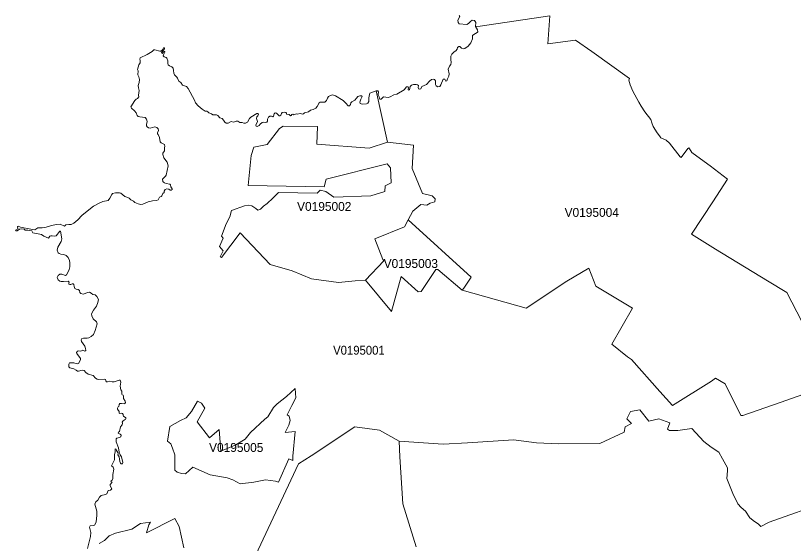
# Model space of a CAD drawing. Extents: x 369010 to 735936, y 6377141 to 6616555.
# Drawn here: x 470305 to 479041, y 6502081 to 6508010 of the extents above; entities that cross this region are included whole.
import ezdxf
from ezdxf.enums import TextEntityAlignment as Align

# ---------------------------------------------------------------- set-up
doc = ezdxf.new("R2010")
doc.units = 0
doc.header["$LTSCALE"] = 40
doc.layers.add('3', color=7, linetype='Continuous', lineweight=13)
doc.layers.add('4', color=7, linetype='Continuous')

msp = doc.modelspace()

# ---------------------------------------------------------------- linework, layer by layer
at = {"layer": '3'}
for points in [[(475288.27, 6508011.78), (475293.89, 6507998.38), (475271.55, 6507958.16), (475274.86, 6507932.51), (475287.77, 6507916.95), (475371.52, 6507910.83), (475391.54, 6507920.26), (475412.73, 6507943.1), (475434.57, 6507957.66), (475457.91, 6507953.69), (475473.63, 6507933.67), (475469.49, 6507887.82), (475469.66, 6507887.82), (475521.79, 6507889.64), (476305.45, 6508008.47), (476281.79, 6507693.85), (476592.44, 6507732.91), (476778.13, 6507606.13), (477199.34, 6507304.42), (477191.73, 6507284.23), (477208.44, 6507231.27), (477235.92, 6507159.44), (477303.94, 6507035.81), (477330.59, 6506992.78), (477372.46, 6506926.91), (477439.32, 6506841.67), (477450.25, 6506804.43), (477464.31, 6506764.71), (477509.5, 6506694.54), (477535.15, 6506657.3), (477551.04, 6506638.43), (477612.44, 6506611.45), (477647.69, 6506578.52), (477767.19, 6506423.28), (477781.75, 6506415.33), (477855.57, 6506515.63), (477864.67, 6506525.39), (477887.18, 6506490.14), (477899.92, 6506472.1), (478080.49, 6506340.86), (478106.47, 6506321.82), (478300.61, 6506172.7), (478134.11, 6505918.32), (477897.44, 6505555.54), (478166.55, 6505386.23), (478748.13, 6505031.55), (478968.25, 6504900.47), (479245.14, 6504363.08)], [(479245.14, 6504363.08), (478968.25, 6504900.47), (478748.13, 6505031.55), (478166.55, 6505386.23), (477897.44, 6505555.54), (478134.11, 6505918.32), (478300.61, 6506172.7), (478106.47, 6506321.82), (478080.49, 6506340.86), (477899.92, 6506472.1), (477887.18, 6506490.14), (477864.67, 6506525.39), (477855.57, 6506515.63), (477781.75, 6506415.33), (477767.19, 6506423.28), (477647.69, 6506578.52), (477612.44, 6506611.45), (477551.04, 6506638.43), (477535.15, 6506657.3), (477509.5, 6506694.54), (477464.31, 6506764.71), (477450.25, 6506804.43), (477439.32, 6506841.67), (477372.46, 6506926.91), (477330.59, 6506992.78), (477303.94, 6507035.81), (477235.92, 6507159.44), (477208.44, 6507231.27), (477191.73, 6507284.23), (477199.34, 6507304.42), (476778.13, 6507606.13), (476592.44, 6507732.91), (476281.79, 6507693.85), (476305.45, 6508008.47), (475521.79, 6507889.64), (475469.66, 6507887.82), (475469.49, 6507887.66)], [(475469.49, 6507887.66), (475493.16, 6507848.27), (475496.97, 6507828.07), (475490.84, 6507819.3), (475450.13, 6507797.95), (475438.38, 6507785.71), (475435.07, 6507748.3), (475418.85, 6507705.44), (475387.07, 6507666.38), (475351.99, 6507641.72), (475331.79, 6507637.25), (475313.92, 6507645.19), (475292.74, 6507660.75), (475282.14, 6507661.91), (475268.74, 6507650.65), (475263.28, 6507633.44), (475250.37, 6507615.07), (475231.33, 6507602.66), (475204.03, 6507577.67), (475194.59, 6507552.51), (475193.43, 6507516.76), (475197.57, 6507483), (475193.1, 6507461.81), (475176.88, 6507439.97), (475164.64, 6507408.85), (475173.57, 6507355.23), (475169.6, 6507330.74), (475157.35, 6507298.3), (475146.76, 6507276.62), (475138.98, 6507274.3), (475125.58, 6507297.14), (475108.2, 6507295.48), (475080.73, 6507232.76), (475069.14, 6507213.23), (475048.45, 6507210.41), (475028.26, 6507219.35), (475020.48, 6507234.91), (475020.48, 6507276.78), (475010.55, 6507291.35), (474994.33, 6507296.97), (474977.62, 6507292.5), (474955.27, 6507273.47), (474921.68, 6507236.56), (474867.56, 6507212.07), (474854.81, 6507188.73), (474843.56, 6507181.95), (474831.31, 6507188.73), (474826.84, 6507203.79), (474829.66, 6507223.32), (474820.22, 6507232.26), (474805.66, 6507237.23), (474772.23, 6507236.56), (474751.54, 6507227.13), (474737.64, 6507214.39), (474731.51, 6507195.35), (474729.86, 6507175.33), (474719.76, 6507171.35), (474715.29, 6507175.82), (474719.26, 6507203.13), (474713.14, 6507210.41), (474695.27, 6507209.92), (474669.61, 6507177.48), (474588.02, 6507126.17), (474554.09, 6507120.71), (474512.72, 6507098.37), (474489.21, 6507089.43), (474438.57, 6507098.37), (474410.1, 6507070.4), (474397.19, 6507070.4), (474392.73, 6507081.65), (474389.42, 6507098.86), (474378.16, 6507120.71), (474379.32, 6507151.99), (474373.2, 6507164.24), (474355.98, 6507163.58), (474483.92, 6506587.46), (474774.71, 6506552.7), (474759.32, 6506291.7), (474874.51, 6506012.5), (474982.25, 6505984.36), (475017.67, 6505950.93), (475013.2, 6505918.16), (474961.73, 6505902.27), (474924.49, 6505881.09), (474856.96, 6505888.04), (474768.09, 6505811.24), (474715.29, 6505715.25), (475421.99, 6505070.12), (475339.74, 6504946.82), (475321.04, 6504926.29), (476037.83, 6504724.21), (476497.44, 6505027.58), (476744.54, 6505173.39), (476822.82, 6504971.31), (477233.1, 6504724.87), (477000.08, 6504320.05), (477178.82, 6504175.24), (477221.19, 6504145.61), (477540.78, 6503787.63), (477682.78, 6503631.72)], [(471975.04, 6507649.16), (471967.76, 6507646.35), (471954.19, 6507624.17), (471936.31, 6507608.45), (471925.72, 6507608.45), (471870.44, 6507625.17), (471856.54, 6507623.51), (471837.51, 6507607.95), (471782.4, 6507573.86), (471704.77, 6507535.96), (471701.96, 6507520.24), (471705.27, 6507503.52), (471704.77, 6507480.19), (471690.87, 6507455.53), (471676.31, 6507404.72), (471680.28, 6507387.5), (471678.63, 6507342.65), (471688.72, 6507320.47), (471695.84, 6507292.5), (471693.69, 6507257.91), (471681.44, 6507226.14), (471684.75, 6507198.17), (471693.19, 6507169.7), (471686.4, 6507116.24), (471690.38, 6507097.71), (471675.31, 6507077.18), (471660.75, 6507069.9), (471643.54, 6507055.34), (471600.51, 6506985.66), (471606.13, 6506968.28), (471640.06, 6506938.16), (471657.94, 6506915.82), (471671.84, 6506888.01), (471683.59, 6506875.6), (471700.31, 6506871.3), (471760.05, 6506866.83), (471776.77, 6506847.79), (471781.24, 6506819.33), (471773.96, 6506788.05), (471774.62, 6506769.68), (471781.57, 6506760.57), (471798.28, 6506749.98), (471817.81, 6506745.51), (471867.47, 6506758.42), (471891.46, 6506752.3), (471906.52, 6506737.24), (471909.83, 6506717.71), (471899.9, 6506691.39), (471898.75, 6506680.3), (471907.19, 6506674.18), (471919.93, 6506641.25), (471929.36, 6506590.93), (471938.96, 6506579.84), (471977.36, 6506560.81), (471981.83, 6506540.78), (471976.86, 6506526.88), (471977.36, 6506492.29), (471960.15, 6506464.82), (471957.33, 6506448.76), (471971.24, 6506410.7), (472008.64, 6506362.21), (472018.74, 6506321.49), (471997.55, 6506218.22), (471989.11, 6506205.31), (471972.39, 6506191.41), (471956.18, 6506170.72), (471958.49, 6506147.88), (471965.77, 6506137.78), (471979.18, 6506130.5), (471998.05, 6506123.38), (472036.61, 6506117.26), (472046.54, 6506107.66), (472048.36, 6506088.13), (472062.76, 6506065.29), (472062.26, 6506055.2), (472054.48, 6506049.07), (472043.23, 6506049.73), (472027.01, 6506058.67), (472004.83, 6506062.97), (471986.3, 6506055.86), (471973.55, 6506038.48), (471972.39, 6506021.76), (471958.99, 6506013.32), (471949.56, 6505986.68), (471940.12, 6505977.74), (471922.74, 6505969.3), (471907.19, 6505941.49), (471889.31, 6505932.56), (471841.32, 6505928.59), (471794.97, 6505918.49), (471735.89, 6505890.69), (471712.88, 6505886.22), (471682.27, 6505894), (471645.36, 6505911.21), (471630.3, 6505925.77), (471598.52, 6505941.99), (471580.15, 6505960.36), (471565.09, 6505968.14), (471532.15, 6505977.57), (471486.97, 6506016.14)], [(472887.8, 6506799.63), (472867.61, 6506801.78), (472850.39, 6506810.72), (472824.74, 6506810.72), (472802.4, 6506824.13), (472782.21, 6506825.29), (472752.08, 6506814.03), (472727.59, 6506819.16), (472692.5, 6506802.94), (472671.15, 6506802.45), (472656.09, 6506813.04), (472642.19, 6506835.22), (472624.31, 6506852.59), (472600.98, 6506861.03), (472576.32, 6506886.03), (472562.42, 6506893.31), (472519.88, 6506894.63), (472505.98, 6506904.73), (472474.7, 6506915.82), (472465.76, 6506927.07), (472454.67, 6506934.35), (472435.14, 6506936.5), (472400.55, 6506958.35), (472357.52, 6506994.6), (472327.4, 6507028.69), (472315.82, 6507059.81), (472244.32, 6507190.39), (472225.95, 6507211.57), (472180.76, 6507227.3), (472160.9, 6507256.92), (472139.72, 6507271.98), (472125.15, 6507305.41), (472115.72, 6507319.48), (472088.25, 6507345.63), (472081.13, 6507364), (472079.48, 6507393.13), (472073.85, 6507417.62), (472060.44, 6507432.69), (472032.47, 6507446.09), (472019.73, 6507457.84), (472015.76, 6507470.59), (472014.1, 6507501.87), (472005.16, 6507533.15), (471995.07, 6507540.43), (471975.54, 6507547.05), (471963.95, 6507556.65), (471965.61, 6507568.9), (471982.82, 6507598.36), (471982.82, 6507606.3), (471975.04, 6507606.8), (471966.11, 6507601.17), (471953.86, 6507584.45), (471946.58, 6507587.27), (471944.92, 6507595.71), (471977.86, 6507638.08), (471979.01, 6507645.36), (471975.04, 6507649.16)], [(472918.08, 6506101.21), (472950.52, 6506437.34), (472981.31, 6506530.52), (473129.27, 6506562.13), (473270.77, 6506740.22), (473309.34, 6506767.19), (473695.29, 6506764.88), (473688.67, 6506566.77), (474275.88, 6506519.27), (474483.92, 6506587.46), (474355.98, 6507163.58), (474284.49, 6507137.43), (474278.36, 6507122.37), (474271.74, 6507086.62), (474270.58, 6507044.74), (474262.8, 6507027.53), (474247.74, 6507017.44), (474197.43, 6507015.78), (474174.59, 6507021.9), (474169.63, 6507039.12), (474181.21, 6507069.9), (474196.93, 6507099.53), (474190.81, 6507110.12), (474169.63, 6507110.12), (474148.94, 6507100.02), (474135.04, 6507080.49), (474114.35, 6507061.46), (474082.57, 6507041.43), (474071.81, 6507029.68), (474066.85, 6507011.31), (474056.75, 6506996.75), (474041.19, 6506994.43), (474013.72, 6507026.87), (473983.1, 6507055.83), (473898.86, 6507108.3), (473864.27, 6507119.55), (473843.58, 6507113.93), (473817.93, 6507101.02), (473807.83, 6507080.99), (473795.59, 6507056.99), (473779.37, 6507038.62), (473726.41, 6507037.96), (473714.16, 6507029.19), (473691.32, 6506987.31), (473677.42, 6506969.44), (473645.47, 6506953.72), (473618.17, 6506947.1), (473593.67, 6506927.57), (473548.99, 6506917.8), (473538.89, 6506904.89), (473529.46, 6506901.58), (473516.05, 6506907.71), (473500.49, 6506908.87), (473467.56, 6506901.58), (473454.65, 6506907.21), (473428.5, 6506896.12), (473417.91, 6506901.58), (473408.31, 6506897.11), (473401.69, 6506886.03), (473392.75, 6506882.72), (473377.69, 6506900.42), (473348.06, 6506901.09), (473347.57, 6506912.84), (473339.79, 6506921.11), (473320.76, 6506925.58), (473300.07, 6506921.11), (473291.79, 6506910.02), (473284.01, 6506889.83), (473274.41, 6506883.21), (473264.98, 6506883.21), (473237.01, 6506913.33), (473221.95, 6506915.65), (473209.7, 6506907.71), (473203.08, 6506879.9), (473195.8, 6506873.78), (473177.93, 6506879.24), (473159.55, 6506879.9), (473145.65, 6506869.81), (473133.9, 6506847.46), (473134.89, 6506824.13), (473125.96, 6506811.71), (473115.37, 6506809.07), (473090.37, 6506813.54), (473076.31, 6506809.07), (473052.97, 6506791.69), (473039.56, 6506776.63), (473016.56, 6506765.04), (473005.97, 6506768.35), (473003.15, 6506778.28), (473021.69, 6506819.66), (473011.1, 6506855.41), (473016.06, 6506870.97), (473026.66, 6506884.37), (473032.78, 6506900.09), (473026.66, 6506908.87), (473015.57, 6506911.68), (472946.39, 6506869.81), (472933.48, 6506855.41), (472908.98, 6506813.04), (472887.8, 6506799.63)], [(479283.53, 6503802.02), (478892.78, 6503665.32), (478472.07, 6503516.7), (478451.55, 6503519.34), (478273.3, 6503873.85), (478166.22, 6503937.9), (478121.36, 6503902.49), (477682.78, 6503631.72), (477540.78, 6503787.63), (477221.19, 6504145.61), (477178.82, 6504175.24), (477000.08, 6504320.05), (477233.1, 6504724.87), (476822.82, 6504971.31), (476744.54, 6505173.39), (476497.44, 6505027.58), (476037.83, 6504724.21), (475321.04, 6504926.29), (475046.47, 6505157.83), (475026.44, 6505156.51), (474861.93, 6504911.56), (474827.84, 6504907.76), (474633.7, 6505077.89), (474525.29, 6504686.31), (474234.5, 6505037.35), (474117.66, 6505030.56), (473933.29, 6505011.2), (473630.41, 6505054.56), (473411.78, 6505142.44), (473164.85, 6505213.28), (472828.71, 6505567.95), (472617.2, 6505291.73), (472604.45, 6505300), (472636.07, 6505368.69), (472594.86, 6505415.03), (472635.73, 6505510.69), (472618.85, 6505533.2), (472669.17, 6505671.72), (472710.05, 6505747.52), (472729.91, 6505822.33), (472876.87, 6505873.14), (472918.75, 6505880.42), (472958.63, 6505872.15), (473002.33, 6505841.2), (473025, 6505823.82), (473054.63, 6505834.08), (473089.38, 6505867.68), (473131.42, 6505898.79), (473193.65, 6505958.87), (473258.86, 6506024.25), (473691.48, 6506013.49), (473724.92, 6506050.07), (473790.13, 6506034.51), (473878.17, 6505971.29), (474293.09, 6505985.19), (474450.65, 6506035.17), (474455.95, 6506098.06), (474524.14, 6506129.67), (474516.85, 6506300.97), (474478.95, 6506342.84), (473793.1, 6506171.21), (473771.42, 6506086.81), (472918.08, 6506101.21)], [(471486.97, 6506016.14), (471471.25, 6506019.45), (471427.22, 6506017.3), (471394.29, 6506010.01), (471386.01, 6505999.92), (471365.33, 6505959.2), (471343.48, 6505933.55), (471284.89, 6505920.14), (471242.52, 6505902.93), (471180.13, 6505867.68), (471126.5, 6505829.28), (471050.04, 6505765.73), (471003.2, 6505716.08), (470958.02, 6505676.52), (470927.9, 6505663.12), (470901.58, 6505663.12), (470871.46, 6505658.65), (470853.09, 6505645.9), (470804.93, 6505667.92), (470763.72, 6505663.94), (470707.12, 6505651.37), (470648.86, 6505633.99), (470605.17, 6505627.04), (470553.53, 6505626.71), (470520.59, 6505604.03), (470476.9, 6505609), (470359.23, 6505633.49), (470335.89, 6505643.75), (470326.62, 6505638.95), (470329.27, 6505613.13), (470305.11, 6505598.74), (470306.6, 6505591.62), (470323.81, 6505593.77), (470350.79, 6505610.65), (470369.82, 6505613.96), (470399.94, 6505610.16), (470412.69, 6505599.89), (470427.41, 6505598.07), (470443.97, 6505600.72), (470487.49, 6505590.46), (470498.91, 6505571.26), (470595.4, 6505550.57), (470622.54, 6505531.38), (470675.67, 6505510.19), (470691.23, 6505531.54), (470700.83, 6505537), (470717.21, 6505537), (470740.38, 6505531.87), (470761.57, 6505535.18), (470801.95, 6505589.47), (470808.74, 6505587.15), (470825.78, 6505503.07), (470818.67, 6505472.13), (470779.94, 6505407.74), (470773.98, 6505373.82), (470783.74, 6505346.01), (470795.66, 6505335.75), (470814.2, 6505329.79), (470847.46, 6505325.32), (470874.28, 6505314.4), (470896.12, 6505292.55), (470910.19, 6505258.29), (470914, 6505233.8), (470914, 6505187.29), (470907.54, 6505156.67), (470897.78, 6505131.02), (470877.59, 6505096.76), (470866.17, 6505088.98), (470824.13, 6505103.71), (470801.78, 6505104.38), (470783.74, 6505092.29), (470772.33, 6505067.8), (470784.9, 6505042.15), (470801.29, 6505028.57), (470818.67, 6505024.11), (470843.82, 6505021.95), (470897.28, 6505025.26), (470908.7, 6505017.15), (470904.23, 6505005.07), (470904.89, 6504994.65), (470914.66, 6504989.85), (470925.58, 6504989.85), (470939.15, 6504998.45), (470953.88, 6504996.96), (470959.34, 6504988.19), (470962.16, 6504966.84), (470972.42, 6504945.66), (470987.15, 6504935.89), (471009.49, 6504931.92), (471021.57, 6504920.5), (471027.04, 6504898.65), (471038.95, 6504886.74), (471064.11, 6504881.77), (471115.41, 6504900.97), (471137.1, 6504903.12), (471155.14, 6504893.36), (471172.02, 6504877.97), (471199.33, 6504871.51), (471218.36, 6504853.47), (471236.89, 6504821.36)], [(471236.89, 6504821.36), (471229.94, 6504788.59), (471214.06, 6504747.71), (471180.79, 6504700.21), (471159.6, 6504659.34), (471160.1, 6504635.83), (471176.49, 6504602.57), (471212.4, 6504568.8), (471222.83, 6504545.8), (471199.82, 6504474.3), (471179.13, 6504427.96), (471154.64, 6504404.62), (471128.49, 6504390.89), (471110.95, 6504387.58), (471069.57, 6504388.24), (471050.54, 6504381.12), (471042.26, 6504367.55), (471046.73, 6504350.01), (471083.8, 6504298.21), (471092.41, 6504272.06), (471094.73, 6504249.22), (471084.8, 6504240.94), (471059.14, 6504251.86), (471044.41, 6504243.75), (471029.68, 6504239.78), (471014.46, 6504244.75), (471001.38, 6504240.94), (470989.96, 6504226.71), (470993.27, 6504213.14), (471032.99, 6504158.02), (471035.15, 6504142.3), (471011.15, 6504103.57), (470998.07, 6504099.77), (470959.34, 6504110.03), (470926.08, 6504111.19), (470909.69, 6504107.88), (470903.24, 6504095.3), (470903.74, 6504065.34), (470914.16, 6504054.42), (470958.85, 6504041.84), (470984, 6504028.77), (470999.23, 6504016.85), (471012.31, 6504016.85), (471052.85, 6504027.61), (471074.7, 6504023.8), (471095.39, 6504000.3), (471119.39, 6503984.08), (471176.15, 6503967.03), (471203.96, 6503937.08), (471222, 6503926.15), (471237.72, 6503924), (471303.76, 6503927.31), (471315.18, 6503920.69), (471320.14, 6503906.62), (471328.25, 6503897.85), (471338.02, 6503896.69), (471365.33, 6503904.97), (471388.33, 6503897.85), (471411.67, 6503897.85), (471467.94, 6503913.57), (471478.86, 6503914.24), (471485.32, 6503905.46), (471486.47, 6503890.73), (471479.85, 6503847.7), (471488.63, 6503804.51), (471497.4, 6503791.43), (471496.74, 6503757.17), (471502.86, 6503748.4), (471513.62, 6503744.59), (471518.09, 6503739.13), (471519.08, 6503710.17), (471537.12, 6503678.06), (471540.43, 6503663.83), (471533.81, 6503652.41), (471524.54, 6503647.44), (471495.08, 6503654.06), (471477.21, 6503651.91), (471467.28, 6503641.98), (471464.63, 6503619.14), (471455.86, 6503613.68), (471450.4, 6503601.1), (471449.9, 6503588.52), (471468.43, 6503563.53), (471470.09, 6503544.5), (471475.55, 6503540.53), (471494.09, 6503544.5), (471507.16, 6503539.54), (471514.94, 6503530.1), (471513.78, 6503518.68), (471517.09, 6503508.92), (471542.25, 6503493.53), (471543.9, 6503482.11), (471539.44, 6503472.34), (471526.86, 6503467.87), (471509.98, 6503455.96), (471501.87, 6503443.87), (471506.83, 6503433.12), (471504.02, 6503411.77), (471483.33, 6503388.93), (471473.57, 6503337.62)], [(477682.78, 6503631.72), (478121.36, 6503902.49), (478166.22, 6503937.9), (478273.3, 6503873.85), (478451.55, 6503519.34), (478472.07, 6503516.7), (478892.78, 6503665.32), (479283.53, 6503802.02)], [(479424.21, 6502550.98), (478768.98, 6502318.78), (478675.97, 6502270.12), (478646.34, 6502301.9), (478603.97, 6502328.71), (478550.68, 6502367.1), (478502.02, 6502442.74), (478454.36, 6502485.94), (478415.3, 6502526.32), (478361.68, 6502640.19), (478291.83, 6502811.32), (478300.77, 6502895.23), (478298.95, 6502930.81), (478245.49, 6503031.6), (478201.3, 6503104.59), (478117.23, 6503162.68), (478036.13, 6503225.08), (477898.27, 6503373.53), (477743.52, 6503351.03), (477648.35, 6503350.86), (477627.17, 6503365.09), (477650.84, 6503436.59), (477529.85, 6503480.78), (477415.99, 6503453.97), (477314.04, 6503579.75), (477212.09, 6503563.2), (477168.39, 6503478.96), (477220.53, 6503429.14), (477151.18, 6503389.59), (477140.92, 6503329.01), (476868, 6503203.4), (476407.41, 6503199.59), (476155.18, 6503210.18), (475896.49, 6503245.77), (475380.12, 6503211.18), (475106.21, 6503194.29), (474614, 6503229.88)], [(475896.49, 6503245.77), (476155.18, 6503210.18), (476407.41, 6503199.59), (476868, 6503203.4), (477140.92, 6503329.01), (477151.18, 6503389.59), (477220.53, 6503429.14), (477168.39, 6503478.96), (477212.09, 6503563.2), (477314.04, 6503579.75), (477415.99, 6503453.97), (477529.85, 6503480.78), (477650.84, 6503436.59), (477627.17, 6503365.09), (477648.35, 6503350.86), (477743.52, 6503351.03), (477898.27, 6503373.53), (478036.13, 6503225.08), (478117.23, 6503162.68), (478201.3, 6503104.59), (478245.49, 6503031.6), (478298.95, 6502930.81), (478300.77, 6502895.23), (478291.83, 6502811.32), (478361.68, 6502640.19), (478415.3, 6502526.32), (478454.36, 6502485.94), (478502.02, 6502442.74), (478550.68, 6502367.1), (478603.97, 6502328.71), (478646.34, 6502301.9), (478675.97, 6502270.12), (478768.98, 6502318.78), (479424.21, 6502550.98)], [(474802.84, 6502042.88), (474652.73, 6502525.82), (474621.62, 6503054.44), (474614, 6503229.88), (474390.57, 6503353.84), (474116.33, 6503390.58), (473623.63, 6503063.38), (473483.78, 6502976.16), (472973.2, 6501889.79)], [(472973.2, 6501889.79), (473483.78, 6502976.16), (473623.63, 6503063.38), (474116.33, 6503390.58), (474390.57, 6503353.84), (474614, 6503229.88), (475106.21, 6503194.29), (475380.12, 6503211.18), (475896.49, 6503245.77)], [(471473.57, 6503337.62), (471459.33, 6503331), (471457.68, 6503319.58), (471481.68, 6503307.66), (471490.45, 6503297.73), (471485.98, 6503279.86), (471473.57, 6503271.58), (471444.11, 6503261.82), (471436.49, 6503254.21), (471436.49, 6503220.94), (471462.64, 6503153.75), (471469.1, 6503106.91), (471481.18, 6503076.95), (471493.76, 6503053.45), (471511.14, 6502989.73), (471507.16, 6502974.67), (471492.6, 6502975.83), (471483.83, 6502981.95), (471477.04, 6502999.83), (471469.76, 6503054.61), (471454.37, 6503075.79), (471456.52, 6503087.21), (471454.37, 6503100.95), (471436.99, 6503125.94), (471435.33, 6503141.33), (471425.57, 6503144.48), (471422.76, 6503134.22), (471425.57, 6503110.22), (471417.29, 6503076.95), (471417.29, 6503019.36), (471381.55, 6502953.49), (471400.58, 6502936.77), (471408.36, 6502916.74), (471398.92, 6502854.68), (471396.11, 6502809.5), (471388.83, 6502791.62), (471378.9, 6502785.5), (471376.58, 6502778.22), (471389.99, 6502768.29), (471369.3, 6502743.63), (471366.48, 6502726.91), (471385.02, 6502693.98), (471379.89, 6502685.04), (471369.96, 6502678.42), (471343.31, 6502675.27), (471328.92, 6502636.88), (471316.01, 6502628.93), (471266.35, 6502619), (471248.48, 6502602.29), (471227.3, 6502567.53), (471206.11, 6502548), (471194.36, 6502523.51), (471216.04, 6502445.06), (471216.7, 6502397.72), (471211.57, 6502321.09), (471190.39, 6502287.17), (471175.99, 6502281.54), (471144.05, 6502280.38), (471135.11, 6502264.33), (471150.83, 6502204.58), (471146.86, 6502157.58), (471111.28, 6502025.34)], [(474614, 6503229.88), (474621.62, 6503054.44), (474652.73, 6502525.82), (474802.84, 6502042.88)], [(472195.33, 6502033.45), (472143.69, 6502271.11), (472093.05, 6502360.98), (471777.43, 6502199.28), (471802.42, 6502288.49), (471819.63, 6502318.28), (471708.91, 6502304.05), (471612.42, 6502240.83), (471428.05, 6502197.13), (471357.22, 6502165.69), (471303.59, 6502112.39), (471245.17, 6502078.96)], [(471245.17, 6502078.96), (471303.59, 6502112.39), (471357.22, 6502165.69), (471428.05, 6502197.13), (471612.42, 6502240.83), (471708.91, 6502304.05), (471819.63, 6502318.28), (471802.42, 6502288.49), (471777.43, 6502199.28), (472093.05, 6502360.98), (472143.69, 6502271.11), (472195.33, 6502033.45)]]:
    msp.add_lwpolyline(points, dxfattribs=at)
for points in [[(474234.5, 6505037.35), (474439.07, 6505254.16), (474428.8, 6505269.55), (474338.77, 6505503.74), (474672.92, 6505638.13), (474715.29, 6505715.25), (474768.09, 6505811.24), (474856.96, 6505888.04), (474924.49, 6505881.09), (474961.73, 6505902.27), (475013.2, 6505918.16), (475017.67, 6505950.93), (474982.25, 6505984.36), (474874.51, 6506012.5), (474759.32, 6506291.7), (474774.71, 6506552.7), (474483.92, 6506587.46), (474275.88, 6506519.27), (473688.67, 6506566.77), (473695.29, 6506764.88), (473309.34, 6506767.19), (473270.77, 6506740.22), (473129.27, 6506562.13), (472981.31, 6506530.52), (472950.52, 6506437.34), (472918.08, 6506101.21), (473771.42, 6506086.81), (473793.1, 6506171.21), (474478.95, 6506342.84), (474516.85, 6506300.97), (474524.14, 6506129.67), (474455.95, 6506098.06), (474450.65, 6506035.17), (474293.09, 6505985.19), (473878.17, 6505971.29), (473790.13, 6506034.51), (473724.92, 6506050.07), (473691.48, 6506013.49), (473258.86, 6506024.25), (473193.65, 6505958.87), (473131.42, 6505898.79), (473089.38, 6505867.68), (473054.63, 6505834.08), (473025, 6505823.82), (473002.33, 6505841.2), (472958.63, 6505872.15), (472918.75, 6505880.42), (472876.87, 6505873.14), (472729.91, 6505822.33), (472710.05, 6505747.52), (472669.17, 6505671.72), (472618.85, 6505533.2), (472635.73, 6505510.69), (472594.86, 6505415.03), (472636.07, 6505368.69), (472604.45, 6505300), (472617.2, 6505291.73), (472828.71, 6505567.95), (473164.85, 6505213.28), (473411.78, 6505142.44), (473630.41, 6505054.56), (473933.29, 6505011.2), (474117.66, 6505030.56)], [(474715.29, 6505715.25), (474672.92, 6505638.13), (474338.77, 6505503.74), (474428.8, 6505269.55), (474439.07, 6505254.16), (474234.5, 6505037.35), (474525.29, 6504686.31), (474633.7, 6505077.89), (474827.84, 6504907.76), (474861.93, 6504911.56), (475026.44, 6505156.51), (475046.47, 6505157.83), (475321.04, 6504926.29), (475339.74, 6504946.82), (475421.99, 6505070.12)], [(473420.39, 6503061.56), (473446.7, 6503338.78), (473331.51, 6503327.36), (473372.56, 6503408.29), (473389.27, 6503463.07), (473378.35, 6503509.41), (473354.35, 6503526.79), (473407.15, 6503631.39), (473453.49, 6503715.8), (473446.87, 6503822.55), (473348.39, 6503730.53), (473241.64, 6503647.44), (473201.76, 6503607.39), (473138.87, 6503503.12), (473106.26, 6503475.65), (472944.07, 6503325.54), (472883.33, 6503251.72), (472779.56, 6503188.67), (472609.75, 6503118.16), (472591.38, 6503362.28), (472482.15, 6503267.94), (472342.96, 6503447.52), (472429.02, 6503600.77), (472394.26, 6503656.38), (472350.07, 6503679.88), (472281.89, 6503562.71), (472221.15, 6503491.87), (472158.92, 6503461.09), (472038.93, 6503392.73), (472010.96, 6503230.54), (472047.7, 6503200.91), (472068.06, 6503152.42), (472094.37, 6503077.28), (472092.05, 6502905.82), (472119.53, 6502880.83), (472170.34, 6502867.26), (472214.69, 6502864.11), (472295.62, 6502937.93), (472491.25, 6502850.87), (472680.92, 6502818.93), (472746.13, 6502796.09), (472826.23, 6502752.07), (472982.8, 6502769.78), (473113.38, 6502796.26), (473223.44, 6502779.71), (473256.21, 6502768.78), (473374.38, 6503031.93), (473418.73, 6503010.75)], [(473420.39, 6503061.56), (473418.73, 6503010.75), (473374.38, 6503031.93), (473256.21, 6502768.78), (473223.44, 6502779.71), (473113.38, 6502796.26), (472982.8, 6502769.78), (472826.23, 6502752.07), (472746.13, 6502796.09), (472680.92, 6502818.93), (472491.25, 6502850.87), (472295.62, 6502937.93), (472214.69, 6502864.11), (472170.34, 6502867.26), (472119.53, 6502880.83), (472092.05, 6502905.82), (472094.37, 6503077.28), (472068.06, 6503152.42), (472047.7, 6503200.91), (472010.96, 6503230.54), (472038.93, 6503392.73), (472158.92, 6503461.09), (472221.15, 6503491.87), (472281.89, 6503562.71), (472350.07, 6503679.88), (472394.26, 6503656.38), (472429.02, 6503600.77), (472342.96, 6503447.52), (472482.15, 6503267.94), (472591.38, 6503362.28), (472609.75, 6503118.16), (472779.56, 6503188.67), (472883.33, 6503251.72), (472944.07, 6503325.54), (473106.26, 6503475.65), (473138.87, 6503503.12), (473201.76, 6503607.39), (473241.64, 6503647.44), (473348.39, 6503730.53), (473446.87, 6503822.55), (473453.49, 6503715.8), (473407.15, 6503631.39), (473354.35, 6503526.79), (473378.35, 6503509.41), (473389.27, 6503463.07), (473372.56, 6503408.29), (473331.51, 6503327.36), (473446.7, 6503338.78)]]:
    msp.add_lwpolyline(points, close=True, dxfattribs=at)

# ---------------------------------------------------------------- texts
at = {"layer": '4'}
for s, p in [('V0195002', (473771.48, 6505816.13)), ('V0195004', (476775.86, 6505749)), ('V0195003', (474743.87, 6505175.19)), ('V0195005', (472783.14, 6503108.68))]:
    msp.add_text(s, height=100, dxfattribs=at).set_placement(p, align=Align.CENTER)
at = {"layer": '4', "width": 0.95}
msp.add_text('V0195001', height=100, dxfattribs=at).set_placement((474160.99, 6504200.86), align=Align.CENTER)

doc.saveas('drawing.dxf')
